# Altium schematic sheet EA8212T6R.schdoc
size 127 x 101 mm
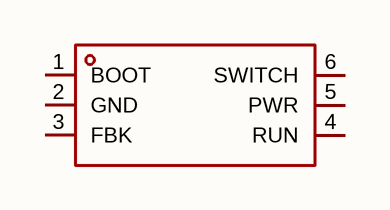
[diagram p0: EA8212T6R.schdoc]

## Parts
U?  ea8212t6r  [SOT-23-6_L2.9-W1.6-P0.95-LS2.8-BL-1]  (value not drawn)

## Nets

Not connected (* = marked no-connect by the designer): U? 1(BOOT) 2(GND) 3(FBK) 4(RUN) 5(PWR) 6(SWITCH)

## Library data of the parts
U? = ea8212t6r: 功能类型:降压型;工作电压:4.5V~18V;输出电压:600mV~12V;输出电流:2A;输出类型:可调;; Manufacturer: everanalog(申风); AddInBom: yes; ModelId: f68680cba8aa4564861882c5d83eaef7; ModelTransform: 114.173,110.236,0,0,0,0,0,0,0; Function: 降压型; Output Current: 2A; Frequency - Switching: 500kHz; Synchronous Rectifier: 是; Number of Outputs: 1; Topology: 降压式; Quiescent Current: 400uA; Switch tube (built-in/external): 内置; Output Type: 可调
